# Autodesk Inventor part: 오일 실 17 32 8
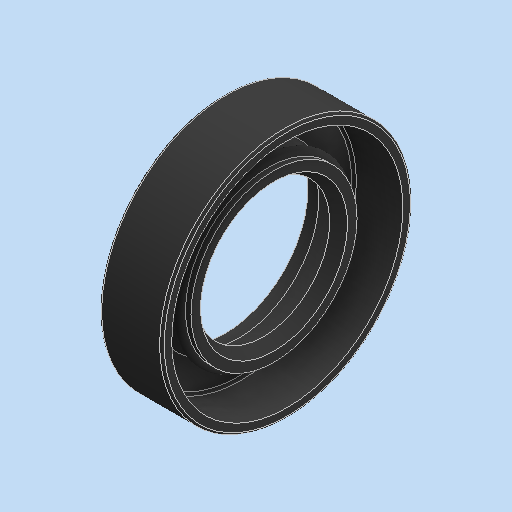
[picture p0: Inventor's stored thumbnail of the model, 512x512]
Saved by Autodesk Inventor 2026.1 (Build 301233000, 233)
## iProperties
Created: 2026-01
Part Number: 오일 실 17 32 8
Material: 고무
Description: 오일-실
Document SubType Name: Modeling
Designer: PC-30
Density: 0.93 g/cm^3
Appearance: 기본값
Author: jhkim
Sending System: Autodesk Inventor 2026
Preprocessor: ST-DEVELOPER v20.1
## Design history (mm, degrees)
feature "Solid1"
node "솔리드1"
